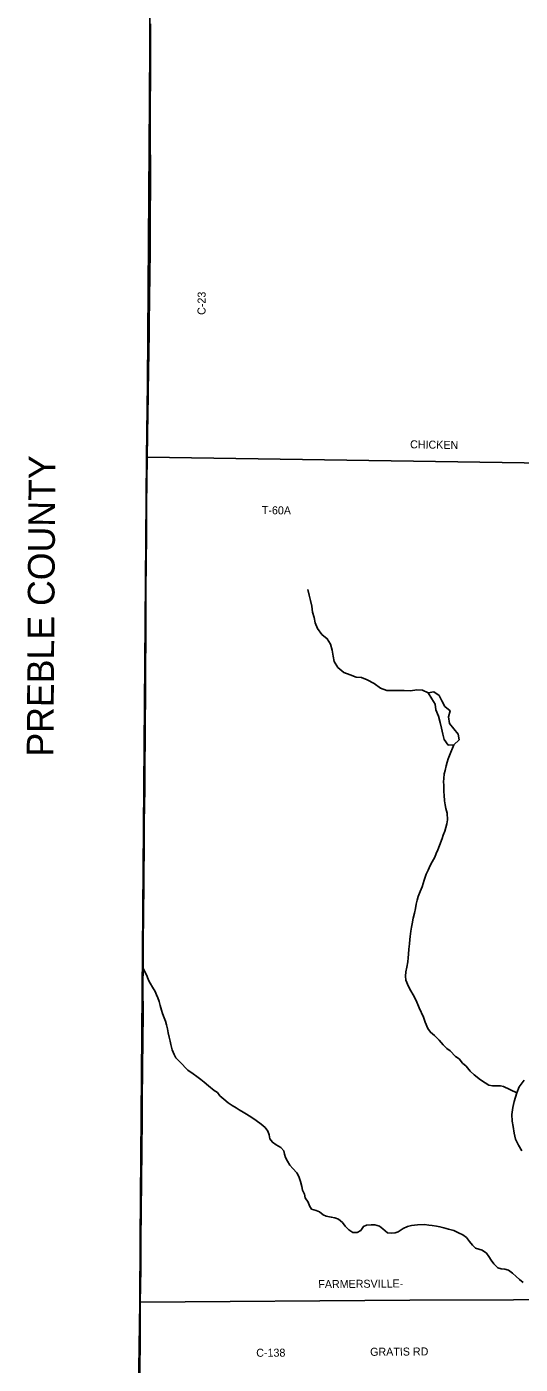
# Model space of a CAD drawing. Extents: x 1312308 to 1684953, y 460642 to 865172.
# Drawn here: x 1410030 to 1414657, y 616453 to 628989 of the extents above; entities that cross this region are included whole.
import ezdxf

# ---------------------------------------------------------------- set-up
doc = ezdxf.new("R2010")
doc.units = 0
for name, color, linetype in [('GM_X_Adjacent_County', 7, 'Continuous'), ('GM_X_Adjacent_County_Text', 7, 'Continuous'), ('GM_X_County', 7, 'Continuous'), ('GM_X_County_Road', 7, 'Continuous'), ('GM_X_County_Road_Text', 7, 'Continuous'), ('GM_X_Minor_Lake', 7, 'Continuous'), ('GM_X_Minor_River', 7, 'Continuous'), ('GM_X_Township', 7, 'Continuous'), ('GM_X_Township_Road', 7, 'Continuous'), ('GM_X_Township_Road_Text', 7, 'Continuous')]:
    doc.layers.add(name, color=color, linetype=linetype)

msp = doc.modelspace()

# ---------------------------------------------------------------- linework, layer by layer
at = {"layer": 'GM_X_Adjacent_County'}
msp.add_lwpolyline([(1411211, 633565), (1411180, 628296), (1411163, 625648), (1411153, 624951), (1411095, 617624), (1411090, 617033), (1411020, 612269), (1411018, 611981), (1410999, 609618), (1410998, 609429), (1410982, 607392), (1410977, 606751), (1410955, 603992), (1410939, 601893), (1410907, 597962), (1410895, 596474), (1410841, 590631), (1410839, 590333), (1410790, 585032), (1410763, 583224)], dxfattribs=at)
at = {"layer": 'GM_X_County'}
msp.add_lwpolyline([(1410955, 603992), (1410977, 606751), (1410982, 607392), (1410998, 609429), (1410999, 609618), (1411018, 611981), (1411020, 612269), (1411090, 617033), (1411095, 617624), (1411153, 624951), (1411163, 625648), (1411180, 628296), (1411211, 633565)], dxfattribs=at)
at = {"layer": 'GM_X_County_Road'}
for points in [[(1411087, 616151), (1411092, 616667), (1411095, 617034), (1411099, 617344), (1411100, 617464), (1411101, 617563), (1411101, 617617), (1411105, 618165), (1411108, 618465), (1411111, 618744), (1411112, 618938), (1411115, 619214), (1411119, 619507), (1411122, 619722), (1411120, 619996), (1411122, 620187), (1411123, 620258), (1411123, 620383), (1411123, 620487), (1411124, 620583), (1411125, 620690), (1411126, 620764), (1411127, 620857), (1411127, 620957), (1411128, 621023), (1411130, 621305), (1411131, 621432), (1411132, 621568), (1411134, 621650), (1411135, 621725), (1411136, 621808), (1411137, 621881), (1411137, 622016), (1411138, 622120), (1411138, 622166), (1411139, 622223), (1411139, 622287), (1411139, 622454), (1411142, 622719), (1411144, 622997), (1411146, 623232), (1411147, 623327), (1411148, 623485), (1411148, 623557), (1411148, 623640), (1411148, 623716), (1411151, 623957), (1411151, 624013), (1411152, 624167), (1411152, 624223), (1411152, 624283), (1411153, 624339), (1411153, 624387), (1411153, 624482), (1411154, 624589), (1411155, 624643), (1411156, 624690), (1411157, 624782), (1411160, 624892), (1411160, 624954), (1411162, 625154), (1411166, 625368), (1411168, 625518), (1411170, 625639), (1411170, 625649), (1411171, 625684), (1411173, 625792), (1411174, 625905), (1411176, 625991), (1411177, 626065), (1411178, 626155), (1411179, 626211), (1411179, 626240), (1411181, 626410), (1411182, 626481), (1411183, 626621), (1411184, 626711), (1411186, 626834), (1411187, 627065), (1411188, 627249), (1411189, 627471), (1411189, 627533), (1411189, 627617), (1411189, 627742), (1411188, 627840), (1411187, 627943), (1411187, 628005), (1411187, 628075), (1411187, 628178), (1411188, 628270), (1411188, 628294), (1411189, 628468), (1411190, 628526), (1411190, 628636), (1411190, 628719), (1411190, 628795), (1411190, 628868), (1411190, 628943), (1411191, 629016)], [(1411095, 617034), (1413623, 617054), (1414595, 617057), (1415550, 617073), (1419221, 617119), (1420340, 617133), (1423023, 617144)]]:
    msp.add_lwpolyline(points, dxfattribs=at)
at = {"layer": 'GM_X_Minor_Lake'}
for points in [[(1413950, 622617), (1413923, 622670), (1413898, 622720), (1413846, 622755), (1413794, 622745), (1413827, 622690), (1413858, 622639), (1413865, 622587), (1413890, 622528), (1413907, 622469), (1413920, 622415), (1413930, 622358), (1413945, 622308), (1413982, 622255), (1414033, 622260)], [(1414033, 622260), (1414084, 622305), (1414075, 622357), (1413993, 622459), (1413986, 622522), (1414001, 622576), (1413950, 622617)]]:
    msp.add_lwpolyline(points, dxfattribs=at)
at = {"layer": 'GM_X_Minor_River'}
for points in [[(1413794, 622745), (1413740, 622770), (1413688, 622773), (1413628, 622764), (1413570, 622768), (1413518, 622769), (1413464, 622768), (1413406, 622767), (1413346, 622790), (1413289, 622832), (1413223, 622867), (1413169, 622889), (1413119, 622894), (1413062, 622913), (1413002, 622936), (1412947, 622984), (1412914, 623039), (1412903, 623089), (1412894, 623145), (1412877, 623202), (1412848, 623253), (1412797, 623294), (1412756, 623349), (1412735, 623402), (1412724, 623452), (1412709, 623503), (1412704, 623559), (1412691, 623611), (1412678, 623662), (1412667, 623714)], [(1414624, 618996), (1414501, 619056), (1414471, 619063), (1414396, 619064), (1414362, 619069), (1414327, 619090), (1414283, 619119), (1414226, 619166), (1414189, 619199), (1414149, 619246), (1414116, 619276), (1414083, 619315), (1414049, 619338), (1414000, 619391), (1413970, 619412), (1413935, 619448), (1413896, 619491), (1413853, 619534), (1413815, 619565), (1413790, 619600), (1413767, 619658), (1413750, 619705), (1413711, 619794), (1413681, 619863), (1413652, 619916), (1413630, 619952), (1413609, 619995), (1413586, 620054), (1413581, 620090), (1413584, 620130), (1413593, 620176), (1413602, 620224), (1413607, 620262), (1413611, 620296), (1413614, 620344), (1413619, 620393), (1413622, 620433), (1413625, 620463), (1413632, 620511), (1413639, 620549), (1413645, 620581), (1413654, 620633), (1413665, 620681), (1413674, 620725), (1413681, 620765), (1413692, 620803), (1413699, 620837), (1413720, 620883), (1413739, 620929), (1413756, 620991), (1413775, 621045), (1413794, 621083), (1413813, 621126), (1413832, 621162), (1413857, 621206), (1413869, 621240), (1413884, 621274), (1413899, 621314), (1413925, 621382), (1413935, 621412), (1413950, 621449), (1413959, 621483), (1413969, 621517), (1413974, 621557), (1413972, 621618), (1413958, 621662), (1413953, 621695), (1413948, 621735), (1413943, 621787), (1413942, 621817), (1413940, 621849), (1413941, 621880), (1413939, 621912), (1413940, 621942), (1413945, 621986), (1413952, 622018), (1413963, 622062), (1413973, 622096), (1413982, 622126), (1413995, 622158), (1414033, 622260)], [(1412457, 618391), (1412448, 618423), (1412440, 618453), (1412413, 618486), (1412369, 618509), (1412334, 618534), (1412310, 618566), (1412303, 618602), (1412290, 618639), (1412264, 618671), (1412227, 618704), (1412181, 618739), (1412140, 618766), (1412090, 618797), (1412059, 618816), (1412023, 618839), (1411993, 618855), (1411956, 618878), (1411918, 618903), (1411877, 618936), (1411839, 618969), (1411818, 618999), (1411786, 619020), (1411735, 619063), (1411695, 619098), (1411662, 619123), (1411626, 619149), (1411589, 619176), (1411539, 619209), (1411465, 619287), (1411429, 619326), (1411412, 619356), (1411395, 619401), (1411382, 619449), (1411374, 619480), (1411365, 619520), (1411356, 619558), (1411349, 619597), (1411339, 619633), (1411330, 619667), (1411319, 619700), (1411303, 619740), (1411292, 619772), (1411281, 619815), (1411272, 619853), (1411260, 619886), (1411247, 619916), (1411233, 619946), (1411210, 619987), (1411187, 620024), (1411173, 620054), (1411160, 620086), (1411141, 620129), (1411122, 620163)], [(1414693, 619117), (1414646, 619052), (1414624, 618996), (1414601, 618915), (1414588, 618859), (1414578, 618795), (1414581, 618730), (1414592, 618680), (1414601, 618618), (1414613, 618563), (1414642, 618506), (1414673, 618452)], [(1414686, 617219), (1414650, 617246), (1414618, 617274), (1414585, 617307), (1414546, 617336), (1414512, 617345), (1414478, 617347), (1414448, 617358), (1414408, 617395), (1414383, 617429), (1414364, 617464), (1414340, 617494), (1414301, 617521), (1414269, 617532), (1414239, 617542), (1414209, 617569), (1414180, 617604), (1414153, 617640), (1414119, 617665), (1414079, 617686), (1414034, 617705), (1413986, 617720), (1413942, 617733), (1413904, 617741), (1413872, 617746), (1413832, 617753), (1413800, 617757), (1413758, 617762), (1413694, 617759), (1413637, 617752), (1413599, 617743), (1413561, 617724), (1413514, 617694), (1413484, 617685), (1413449, 617681), (1413413, 617684), (1413368, 617723), (1413336, 617748), (1413295, 617761), (1413258, 617761), (1413216, 617756), (1413186, 617743), (1413163, 617707), (1413127, 617687), (1413088, 617688), (1413051, 617713), (1413016, 617748), (1412992, 617780), (1412953, 617813), (1412919, 617824), (1412885, 617832), (1412839, 617841), (1412809, 617854), (1412776, 617881), (1412744, 617893), (1412700, 617908), (1412680, 617939), (1412669, 617971), (1412642, 618012), (1412635, 618048), (1412617, 618086), (1412610, 618119), (1412597, 618165), (1412582, 618212), (1412564, 618248), (1412525, 618289), (1412498, 618320), (1412474, 618356), (1412457, 618391)]]:
    msp.add_lwpolyline(points, dxfattribs=at)
at = {"layer": 'GM_X_Township'}
msp.add_lwpolyline([(1443487, 629689), (1443383, 625252), (1443279, 619937), (1443263, 619245), (1443164, 614625), (1443063, 609310), (1440472, 609335), (1437771, 609361), (1435200, 609380), (1434197, 609393), (1430058, 609438), (1427248, 609465), (1424759, 609498), (1422201, 609520), (1411036, 609618), (1410999, 609618), (1411018, 611981), (1411020, 612269), (1411090, 617033), (1411095, 617624), (1411153, 624951), (1411163, 625648), (1411180, 628296), (1411211, 633565)], dxfattribs=at)
at = {"layer": 'GM_X_Township_Road'}
msp.add_lwpolyline([(1411160, 624954), (1415734, 624885), (1416715, 624877)], dxfattribs=at)

# ---------------------------------------------------------------- texts
at = {"layer": 'GM_X_Adjacent_County_Text'}
msp.add_text('PREBLE COUNTY', height=250, rotation=89.6123, dxfattribs=at).set_placement((1410280, 622147))
at = {"layer": 'GM_X_County_Road_Text'}
for s, rotation, p in [('C-23', 89.6615, (1411706, 626288)), ('FARMERSVILLE-', 0.5213, (1412764, 617166)), ('C-138', 0.2753, (1412182, 616523)), ('GRATIS RD', 0.3926, (1413250, 616532))]:
    msp.add_text(s, height=75, rotation=rotation, dxfattribs=at).set_placement(p)
at = {"layer": 'GM_X_Township_Road_Text'}
for s, rotation, p in [('CHICKEN', 359.0715, (1413624, 625038)), ('T-60A', 359.2262, (1412234, 624421))]:
    msp.add_text(s, height=75, rotation=rotation, dxfattribs=at).set_placement(p)

doc.saveas('drawing.dxf')
